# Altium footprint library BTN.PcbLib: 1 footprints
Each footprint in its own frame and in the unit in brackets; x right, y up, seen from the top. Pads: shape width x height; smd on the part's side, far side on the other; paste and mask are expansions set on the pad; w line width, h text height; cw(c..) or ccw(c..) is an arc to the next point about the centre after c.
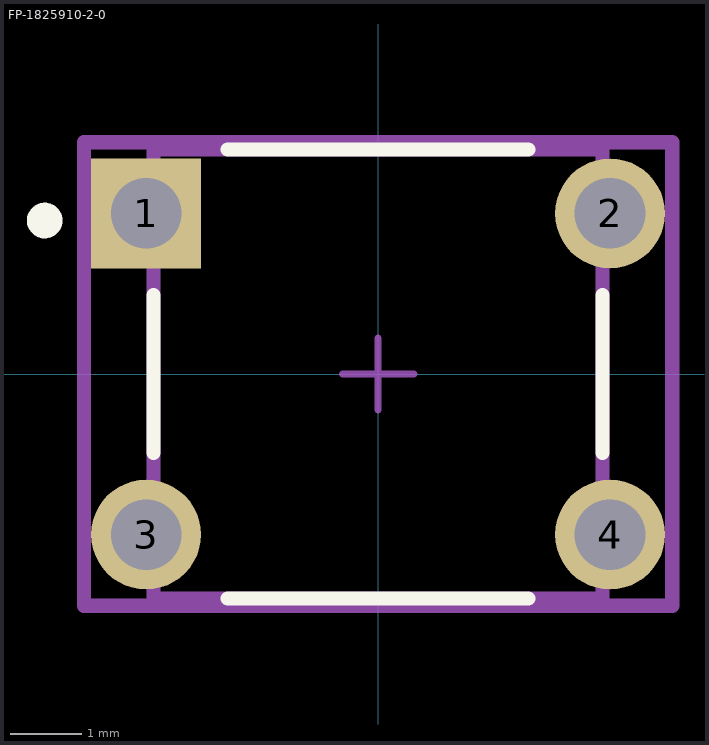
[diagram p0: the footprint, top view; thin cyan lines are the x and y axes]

## FP-1825910-2-0 [mm]
pads (4):
  rect 1.54x1.54 hole 0.99 paste-1000 mask+0: 1(-3.25,2.25)
  round 1.54 hole 0.99 paste-1000 mask+0: 2(3.25,2.25) 3(-3.25,-2.25) 4(3.25,-2.25)
Top Overlay:
  circle w0.25: c-4.67,2.15 r0.125
  lines w0.2: -3.145,-1.105 -3.145,1.105 ; -2.105,-3.145 2.105,-3.145 ; -2.105,3.145 2.105,3.145 ; 3.145,-1.105 3.145,1.105
Top Assembly:
  lines w0.2: -4.12,-3.245 -4.12,3.245 4.12,3.245 4.12,-3.245 -4.12,-3.245
  text ".Designator" at 0,0.188 h1
Top 3D Body:
  lines w0.2: -3.145,-3.145 -3.145,3.145 3.145,3.145 3.145,-3.145 -3.145,-3.145
Top Courtyard:
  lines w0.2: -4.12,-3.245 -4.12,3.245 4.12,3.245 4.12,-3.245 -4.12,-3.245
Top Component Center:
  lines w0.1: -0.5,0 0.5,0 ; 0,-0.5 0,0.5
3D body "Switch_TE_1825910-2_eec.STEP": height 0.25, standoff 0, extent -4.12,-3.245 4.12,3.245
